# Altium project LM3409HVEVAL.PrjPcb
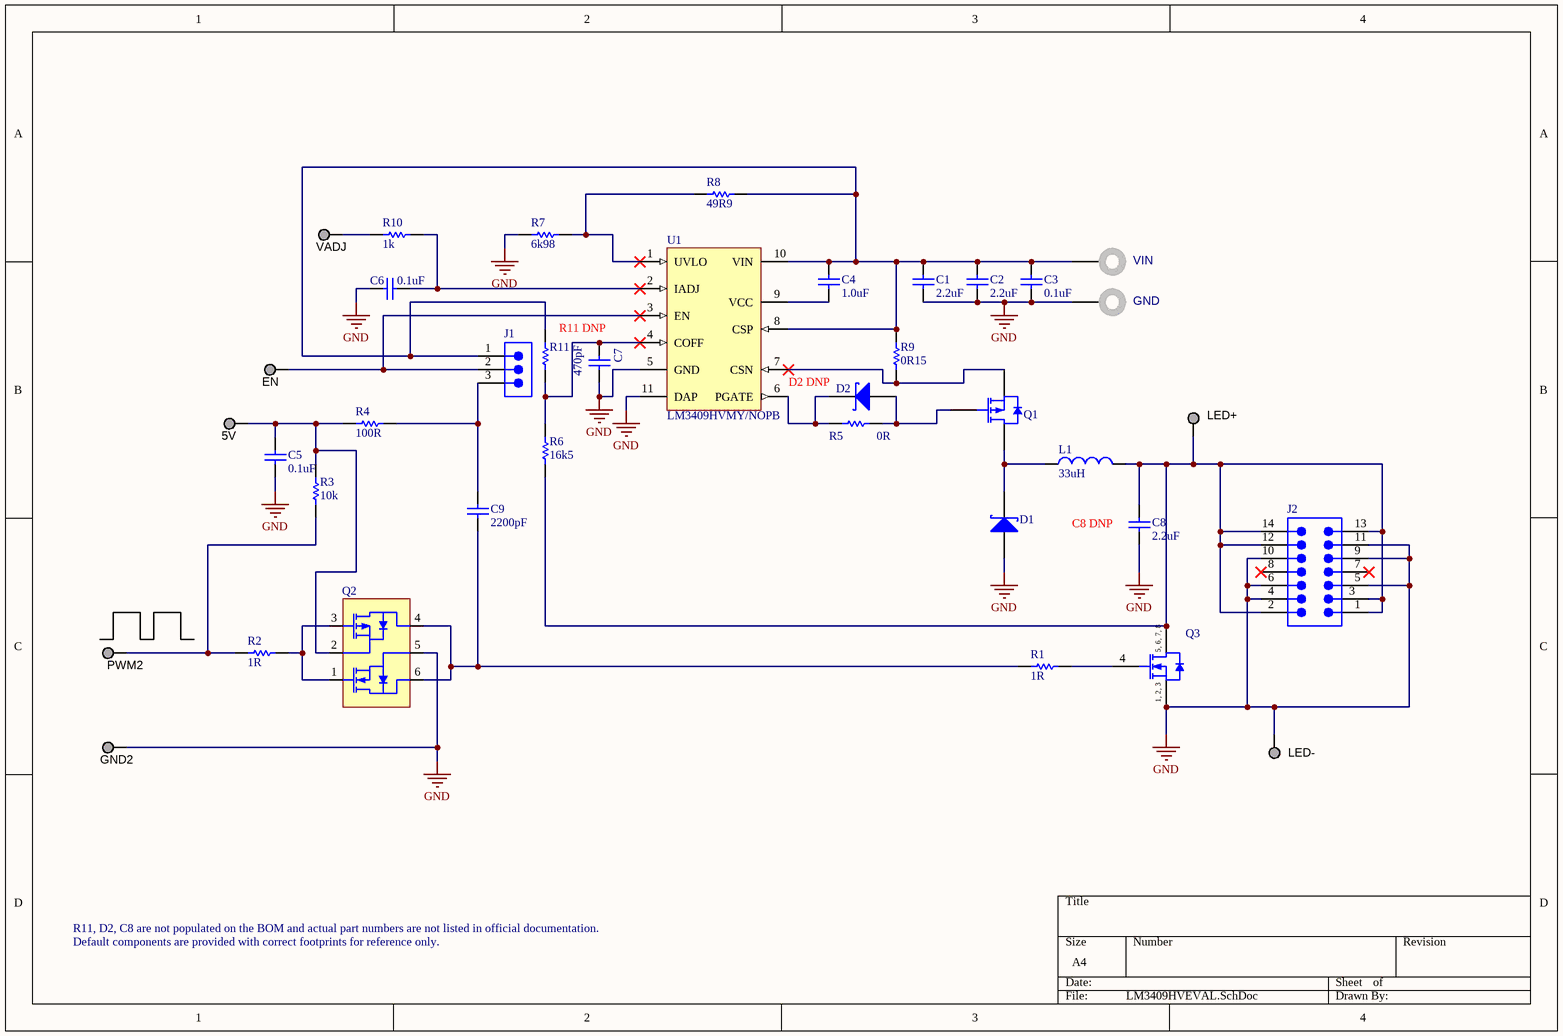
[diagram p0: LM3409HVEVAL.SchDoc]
1 sheet, 38 parts. Net scope: global (net labels, ports and power ports of the same name join across sheets).
Board file: LM3409HVEVAL.PcbDoc

## Sheet LM3409HVEVAL.SchDoc: LM3409HV Evaluation Board
size A4

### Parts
5V  1502-2  [KSTN-1502-2]  (value not drawn)
C1  2.2uF  [CAPC4532X270X30LL40]
C2  2.2uF  [CAPC4532X270X30LL40]
C3  0.1uF  [CAPC1608X90X35LL10T15]
C4  1.0uF  [CAPC1608X90X20LL10]
C5  0.1uF  [CAPC3216X95X55LL15T25]
C6  0.1uF  [CAPC1608X90X35LL10T15]
C7  470pF  [CAPC1608X90X20LL10]
C8  2.2uF  [CAPC4532X270X30LL40]
C9  2200pF  [CAPC1608X90X35LL10T15]
D1  SS3H10-E3/57T  [VSH-DO-214AB-2_V]  (value not drawn)
D2  SS3H10-E3/57T  [VSH-DO-214AB-2_V]  (value not drawn)
EN  1502-2  [KSTN-1502-2]  (value not drawn)
GND  575-8  [KSTN-575-8]  (value not drawn)
GND2  1502-2  [KSTN-1502-2]  (value not drawn)
J1  22-28-4033  [MOLX-22-28-4033_V]  (value not drawn)
J2  TSSH-107-01-S-D-RA  [SMTC-TSSH-107-01-S-D-RA]  (value not drawn)
L1  33uH  [TDK-SLF12575-H_V]
LED+  1502-2  [KSTN-1502-2]  (value not drawn)
LED-  1502-2  [KSTN-1502-2]  (value not drawn)
PWM2  1502-2  [KSTN-1502-2]  (value not drawn)
Q1  ZXMP10A18KTC  [DIOD-TO252-3_V]  (value not drawn)
Q2  FDC6333C  [FAIR-SOT23-6_V]  (value not drawn)
Q3  FDS3672  [FAIR-SO8_V]  (value not drawn)
R1  1R  [RESC1609X50X30LL10T20]
R2  1R  [RESC1609X50X30LL10T20]
R3  10k  [RESC1609X55X30LL10T20]
R4  100R  [RESC1609X50X30LL10T20]
R5  0R  [RESC1609X50X30LL10T20]
R6  16k5  [RESC1609X50X30LL10T20]
R7  6k98  [RESC1609X50X30LL10T20]
R8  49R9  [RESC1609X50X30LL10T20]
R9  0R15  [RESC6432X89X76LL25T25]
R10  1k  [RESC1609X50X30LL10T20]
R11  16k5  [RESC1609X50X30LL10T20]  (value not drawn)
U1  LM3409HVMY/NOPB  [DGQ0010A_N]
VADJ  1502-2  [KSTN-1502-2]  (value not drawn)
VIN  575-8  [KSTN-575-8]  (value not drawn)

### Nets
GND: C1.2 C2.2 C3.2 C5.2 C6.1 C7.2 C8.2 D1.1(A) GND.1 GND2.1 J2.4 J2.5 J2.6 J2.9 J2.10 J2.11 LED-.1 Q2.5(S) Q3.1(S) Q3.2(S) Q3.3(S) R7.1 U1.5(GND) U1.11(DAP)
Net5V_1: 5V.1 C5.1 Q2.2(S) R3.2 R4.1
NetC1_1: C1.1 C2.1 C3.1 C4.1 J1.1 R8.2 R9.2 R11.2 U1.8(CSP) U1.10(VIN) VIN.1
NetC4_2: C4.2 U1.9(VCC)
NetC6_2: C6.2 R10.2 U1.2(IADJ)
NetC7_1: C7.1 R6.2 R11.1 U1.4(COFF)
NetC8_1: C8.1 J2.1 J2.2 J2.12 J2.13 J2.14 L1.2 LED+.1 Q3.5(D) Q3.6(D) Q3.7(D) Q3.8(D) R6.1
NetC9_1: C9.1 J1.3 R4.2
NetC9_2: C9.2 Q2.4(D) Q2.6(D) R1.1
NetD1_2: D1.2(K) L1.1 Q1.3(D)
NetD2_1: D2.1(A) Q1.1(G) R5.2
NetD2_2: D2.2(K) R5.1 U1.6(PGATE)
NetEN_1: EN.1 J1.2 U1.3(EN)
NetPWM2_1: PWM2.1 R2.1 R3.1
NetQ1_2: Q1.2(S) R9.1 U1.7(CSN)
NetQ2_1: Q2.1(G) Q2.3(G) R2.2
NetQ3_4: Q3.4(G) R1.2
NetR7_2: R7.2 R8.1 U1.1(UVLO)
NetR10_1: R10.1 VADJ.1

Not connected (* = marked no-connect by the designer): J2 3 7* 8*

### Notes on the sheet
- R11 DNP
- D2 DNP
- (near C8) C8 DNP
- R11, D2, C8 are not populated on the BOM and actual part numbers are not listed in official documentation.
- Default components are provided with correct footprints for reference only.

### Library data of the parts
5V EN GND2 LED+ LED- PWM2 VADJ = CMP-1672-00001-3: turret; Manufacturer: Keystone
C1 C2 C8 = CMP-1662-00004-2: 2.2μF X7R 10% 100V; PartNumber: GRM43ER72A225KA01L; Manufacturer: Murata
C3 = CMP-1662-00005-2: 0.1μF X7R 10% 100V; Manufacturer: Murata; PartNumber: GRM188R72A104KA35D
C4 = CMP-1663-00002-2: 1.0μF X7R 10% 16V; Manufacturer: TDK; PartNumber: C1608X7R1C105K080AC
C5 = CMP-1662-00007-2: 0.1μF X7R 10% 50V; PartNumber: GRM319R71H104KA01D; Manufacturer: Murata
C6 = CMP-1662-00003-2: 0.1μF X7R 10% 50V; Manufacturer: Murata; PartNumber: GCM188R71H104KA57D
C7 = CMP-1663-00001-2: 470pF X7R 10% 50V; PartNumber: C1608X7R1H471K; Manufacturer: TDK
C9 = CMP-1662-00006-2: 2200pF X7R 10% 50V; Manufacturer: Murata; PartNumber: GRM188R71H222KA01D
D1 D2 = CMP-1666-00013-2: Schottky 100V 3A; Manufacturer: Vishay Semiconductor
GND VIN = CMP-1672-00007-3: banana jack; Manufacturer: Keystone
J1 = CMP-1676-00001-3: 3 pin header; Manufacturer: Molex
J2 = CMP-1681-00003-3: 2x7 pin RA shrouded; Manufacturer: Samtec
L1 = CMP-1663-00003-2: 33 μH 20% 3.2A; PartNumber: SLF12575T-330M3R2-H; Manufacturer: TDK
Q1 = CMP-1668-00001-3: PMOS 100V 3.8A; Manufacturer: Zetex
Q2 = CMP-1670-00004-2: CMOS 30V 2A; Manufacturer: Fairchild Semiconductor
Q3 = CMP-1670-00003-2: NMOS 100V 7.5A; Manufacturer: Fairchild Semiconductor
R1 R2 = CMP-1666-00006-2: 1Ω 1%; PartNumber: CRCW06031R00FNEA; Manufacturer: Vishay Semiconductor
R3 = CMP-1666-00005-2: 10kΩ 1%; PartNumber: CRCW060310K0FKEA; Manufacturer: Vishay Semiconductor
R4 = CMP-1666-00008-2: 100Ω 1%; PartNumber: CRCW0603100RFKEA; Manufacturer: Vishay Semiconductor
R5 = CMP-1666-00007-2: 0Ω 1%; Manufacturer: Vishay Semiconductor; PartNumber: CRCW06030000Z0EA
R6 R11 = CMP-1666-00002-2: 16.5kΩ 1%; Manufacturer: Vishay Semiconductor; PartNumber: CRCW060316K5FKEA
R7 = CMP-1666-00001-2: 6.98kΩ 1%; PartNumber: CRCW06036K98FKEA; Manufacturer: Vishay Semiconductor
R8 = CMP-1666-00004-2: 49.9kΩ 1%; PartNumber: CRCW060349K9FKEA; Manufacturer: Vishay Semiconductor
R9 = CMP-1666-00009-2: 0.15Ω 1% 1W; PartNumber: WSL2512R1500FEA; Manufacturer: Vishay Semiconductor
R10 = CMP-1666-00003-2: 1kΩ 1%; PartNumber: CRCW06031K00FKEA; Manufacturer: Vishay Semiconductor
U1 = CMP-0063-01397-3: PFET Buck Controller for High Power LED Drives, 10-pin eMSOP, Pb-Free; Manufacturer: Texas Instruments; CompType: MiscPower; PackageTopMarking: ZXTT*SYHB; PowerWise: Y

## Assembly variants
LM3409HVEVAL Deployment BOM: not fitted C8 D2 R11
